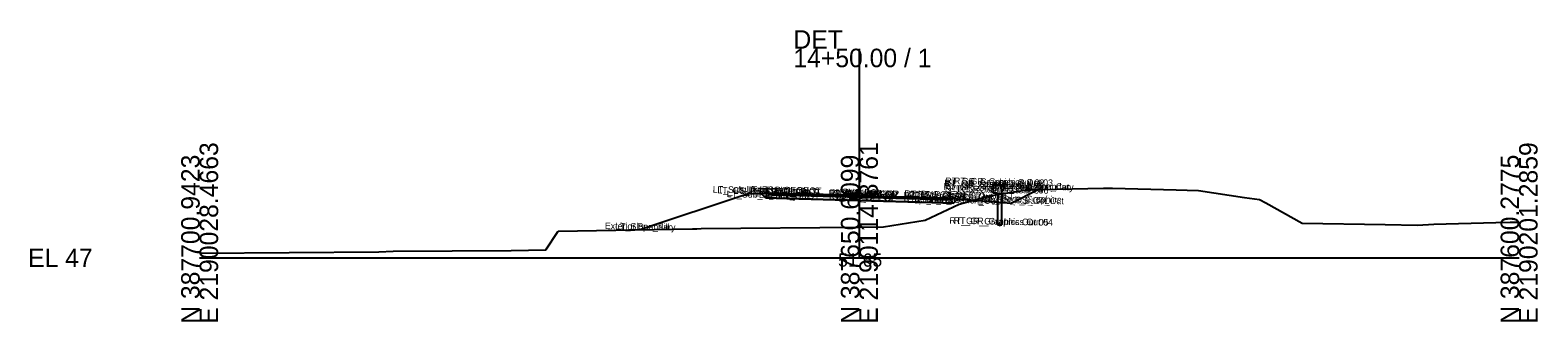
# Model space of a CAD drawing. Extents: x -26 to 1203, y -10 to 9543.
# Drawn here: x -25.7 to 202.8, y 4490.3 to 4534.5 of the extents above; entities that cross this region are included whole.
import ezdxf

# ---------------------------------------------------------------- set-up
doc = ezdxf.new("R2010")
doc.units = 0
for name, color, linetype in [('Default', 7, 'Continuous'), ('Exist Cross Section Cell', 7, 'Continuous'), ('Exist XS Center Line Elevation Label', 7, 'Continuous'), ('Exist XS Ground Line', 7, 'Continuous'), ('Prop CMT Guardrail Graphics', 7, 'Continuous'), ('Prop CMT Pvmt Course 1', 7, 'Continuous'), ('Prop CMT Pvmt Course 2', 7, 'Continuous'), ('Prop CMT Pvmt Course 3', 7, 'Continuous'), ('Prop CMT Pvmt Surface', 7, 'Continuous'), ('Prop CMT Pvmt Surface Shoulder', 7, 'Continuous'), ('Prop CMT Shld Paved Course 1', 7, 'Continuous'), ('Prop CMT Shld Paved Course 2', 7, 'Continuous'), ('Prop CMT Shld Paved Course 3', 7, 'Continuous'), ('Prop CMT Slope Grass', 7, 'Continuous'), ('Prop CMT Subgrade Earthwork', 7, 'Continuous'), ('Scratch_Level_0', 7, 'Continuous')]:
    doc.layers.add(name, color=color, linetype=linetype)

msp = doc.modelspace()

# ---------------------------------------------------------------- linework, layer by layer
at = {"layer": 'Exist Cross Section Cell'}
for p, q in [((100, 4500), (100, 4531.65)), ((0, 4500), (100, 4500)), ((100, 4500), (200, 4500))]:
    msp.add_line(p, q, dxfattribs=at)
at = {"layer": 'Exist XS Ground Line'}
for p, q in [((115.15, 4508.12), (119.71, 4509.4)), ((119.71, 4509.4), (124.76, 4510.19)), ((124.76, 4510.19), (126.04, 4510.29)), ((126.04, 4510.29), (127.51, 4510.33)), ((127.51, 4510.33), (137.02, 4510.52)), ((137.02, 4510.52), (138.38, 4510.55)), ((138.38, 4510.55), (148.04, 4510.26)), ((148.04, 4510.26), (149.7, 4510.21)), ((149.7, 4510.21), (151.41, 4510.18)), ((151.41, 4510.18), (158.37, 4509.14)), ((158.37, 4509.14), (160.65, 4508.8)), ((109.97, 4505.7), (115.15, 4508.12)), ((160.65, 4508.8), (161.63, 4508.3)), ((161.63, 4508.3), (167.13, 4505.26)), ((74.71, 4504.37), (75.38, 4504.39)), ((75.38, 4504.39), (76.04, 4504.41)), ((76.04, 4504.41), (100, 4504.65)), ((100, 4504.65), (103.65, 4504.69)), ((103.65, 4504.69), (109.97, 4505.7)), ((167.13, 4505.26), (179.69, 4505.06)), ((179.69, 4505.06), (184.61, 4504.95)), ((184.61, 4504.95), (187.08, 4505.09)), ((187.08, 4505.09), (196.47, 4505.34)), ((196.47, 4505.34), (198.66, 4505.41)), ((198.66, 4505.41), (200, 4505.38)), ((52.47, 4501.19), (54.35, 4504.03)), ((54.35, 4504.03), (74.71, 4504.37)), ((0, 4500.7), (27.17, 4500.92)), ((27.17, 4500.92), (29.32, 4501)), ((29.32, 4501), (47.24, 4501.11)), ((47.24, 4501.11), (52.47, 4501.19))]:
    msp.add_line(p, q, dxfattribs=at)
at = {"layer": 'Prop CMT Guardrail Graphics'}
for points in [[(121.59, 4511), (120.26, 4511), (119.99, 4510.71)], [(119.99, 4510.71), (120.26, 4510.42)], [(120.26, 4510.42), (119.99, 4510.13)], [(119.99, 4510.13), (120.26, 4509.84), (120.92, 4509.84)], [(120.92, 4509.84), (120.92, 4505)], [(121.59, 4505), (121.59, 4511)], [(120.92, 4505), (121.59, 4505)]]:
    msp.add_lwpolyline(points, dxfattribs=at)
at = {"layer": 'Prop CMT Pvmt Course 1'}
for points in [[(100, 4509.42), (89, 4509.73)], [(89, 4509.73), (89, 4509.48)], [(89, 4509.48), (100, 4509.17)], [(100, 4509.17), (100, 4509.42)], [(100, 4509.42), (111, 4509.12)], [(100, 4509.17), (100, 4509.42)], [(111, 4508.87), (100, 4509.17)], [(111, 4509.12), (111, 4508.87)]]:
    msp.add_lwpolyline(points, dxfattribs=at)
msp.add_lwpolyline([(100, 4509.17), (100, 4509.3), (100, 4509.3), (100, 4509.17)], close=True, dxfattribs=at)
msp.add_lwpolyline([(100, 4509.17), (100, 4509.3), (100, 4509.3), (100, 4509.17)], close=True, dxfattribs=at)
at = {"layer": 'Prop CMT Pvmt Course 2'}
for points in [[(89, 4509.48), (100, 4509.17)], [(100, 4509.17), (89, 4509.48)], [(89, 4509.48), (89, 4509.48)], [(100, 4509.17), (100, 4509.17)], [(111, 4508.87), (100, 4509.17)], [(100, 4509.17), (100, 4509.17)], [(100, 4509.17), (111, 4508.87)], [(111, 4508.87), (111, 4508.87)]]:
    msp.add_lwpolyline(points, dxfattribs=at)
at = {"layer": 'Prop CMT Pvmt Course 3'}
for points in [[(100, 4509.17), (89, 4509.48)], [(89, 4509.48), (89, 4508.98)], [(89, 4508.98), (100, 4508.67)], [(100, 4508.67), (100, 4509.17)], [(100, 4509.17), (111, 4508.87)], [(100, 4508.67), (100, 4509.17)], [(111, 4508.37), (100, 4508.67)], [(111, 4508.87), (111, 4508.37)]]:
    msp.add_lwpolyline(points, dxfattribs=at)
at = {"layer": 'Prop CMT Pvmt Surface'}
for points in [[(100, 4509.42), (89, 4509.73)], [(100, 4509.42), (111, 4509.12)]]:
    msp.add_lwpolyline(points, dxfattribs=at)
at = {"layer": 'Prop CMT Pvmt Surface Shoulder'}
for points in [[(89, 4509.73), (87, 4509.78)], [(111, 4509.12), (113, 4509.06)]]:
    msp.add_lwpolyline(points, dxfattribs=at)
at = {"layer": 'Prop CMT Shld Paved Course 1'}
for points in [[(89, 4509.73), (87, 4509.78), (86.76, 4509.54)], [(86.76, 4509.54), (89, 4509.48)], [(89, 4509.48), (89, 4509.73)], [(111, 4509.12), (113, 4509.06), (113.26, 4508.81)], [(111, 4508.87), (111, 4509.12)], [(113.26, 4508.81), (111, 4508.87)]]:
    msp.add_lwpolyline(points, dxfattribs=at)
at = {"layer": 'Prop CMT Shld Paved Course 2'}
for points in [[(89, 4509.48), (86.76, 4509.54)], [(86.76, 4509.54), (86.76, 4509.54)], [(86.76, 4509.54), (89, 4509.48)], [(89, 4509.48), (89, 4509.48)], [(111, 4508.87), (113.26, 4508.81)], [(113.26, 4508.81), (111, 4508.87)], [(111, 4508.87), (111, 4508.87)], [(113.26, 4508.81), (113.26, 4508.81)]]:
    msp.add_lwpolyline(points, dxfattribs=at)
at = {"layer": 'Prop CMT Shld Paved Course 3'}
for points in [[(89, 4509.48), (86.76, 4509.54), (86.26, 4509.55), (85.77, 4509.07)], [(85.77, 4509.07), (89, 4508.98)], [(89, 4508.98), (89, 4509.48)], [(111, 4508.87), (113.26, 4508.81), (113.76, 4508.79), (114.27, 4508.28)], [(111, 4508.37), (111, 4508.87)], [(114.27, 4508.28), (111, 4508.37)]]:
    msp.add_lwpolyline(points, dxfattribs=at)
at = {"layer": 'Prop CMT Slope Grass'}
for points in [[(87, 4509.78), (83, 4509.65), (66.74, 4504.24)], [(113, 4509.06), (122.99, 4508.26), (123, 4508.26), (127.11, 4510.32)], [(113, 4509.06), (119.99, 4508.5)], [(122.99, 4508.26), (123, 4508.26), (127.11, 4510.32)], [(119.99, 4508.5), (122.99, 4508.26)]]:
    msp.add_lwpolyline(points, dxfattribs=at)
at = {"layer": 'Prop CMT Subgrade Earthwork'}
for points in [[(85.77, 4509.07), (85.12, 4509.72)], [(89, 4508.98), (85.77, 4509.07)], [(100, 4508.67), (89, 4508.98)], [(100, 4508.67), (111, 4508.37)], [(111, 4508.37), (114.27, 4508.28)], [(114.27, 4508.28), (114.9, 4508.91)]]:
    msp.add_lwpolyline(points, dxfattribs=at)

# ---------------------------------------------------------------- texts
at = {"layer": 'Default'}
msp.add_text('-', height=0.0001, dxfattribs=at).set_placement((0, 4500))
at = {"layer": 'Exist Cross Section Cell'}
for s, p in [('DET', (90, 4531.65)), ('14+50.00 / 1', (90, 4528.85)), ('EL 47', (-26, 4498.6))]:
    msp.add_text(s, height=2.8, dxfattribs=at).set_placement(p)
for s, p in [('E 2190028.4663', (2.8, 4490)), ('E 2190114.8761', (102.8, 4490)), ('E 2190201.2859', (202.8, 4490)), ('N 387700.9423', (0, 4490)), ('N 387650.6099', (100, 4490)), ('N 387600.2775', (200, 4490))]:
    msp.add_text(s, height=2.8, rotation=90, dxfattribs=at).set_placement(p)
at = {"layer": 'Exist XS Center Line Elevation Label'}
msp.add_text('51.65', height=2, dxfattribs=at).set_placement((96.77, 4498.65))
at = {"layer": 'Scratch_Level_0'}
for s, p in [('RT_GR_Graphics Out 08', (112.7, 4510.27)), ('RT_GR_Graphics Out 01', (112.87, 4510.85)), ('RT_GR_Graphics Out 09', (112.97, 4510.56)), ('RT_GR_Graphics Out 02', (113, 4511.15)), ('RT_GR_Graphics Out 03', (114.32, 4511.15)), ('Exterior Boundary', (121.77, 4510.42)), ('RT_Slope_Cut', (123.05, 4510.4)), ('LT_Sub_Trench_Out_DLT', (77.77, 4509.87)), ('LT_GS_OS_CTL', (78.46, 4509.74)), ('LT_Sub_Trench_Out', (79.88, 4509.18)), ('LT_PS3_Shelf_Out', (80.91, 4509.66)), ('LT_PS3_OEOP', (82.54, 4509.62)), ('LT_PS2_OEOP', (82.54, 4509.62)), ('LT_PS1_OEOP', (82.91, 4509.86)), ('LT_PV2_OEOT', (84.75, 4509.56)), ('LT_PV3_OEOT', (84.75, 4509.56)), ('LT_Sub_OEOT', (84.77, 4509.06)), ('LT_PV1_OEOT', (84.87, 4509.81)), ('RT_PV2_OEEOP', (95.33, 4509.26)), ('RT_PV3_OEEOP', (95.33, 4509.26)), ('RT_Sub_OEEOP', (95.36, 4508.76)), ('LT_PV2_OEEOP', (95.39, 4509.26)), ('LT_PV3_OEEOP', (95.39, 4509.26)), ('LT_Sub_OEEOP', (95.42, 4508.76)), ('RT_PV1_OEEOP', (95.45, 4509.39)), ('LT_PV1_OEEOP', (95.51, 4509.39)), ('RT_PV2_IEEOP', (95.71, 4509.26)), ('LT_PV2_IEEOP', (95.77, 4509.26)), ('RT_PV1_IEEOP', (95.83, 4509.38)), ('LT_PV1_IEEOP', (95.89, 4509.38)), ('PV2_PGL', (97.35, 4509.23)), ('PV1_PGL', (97.47, 4509.47)), ('RT_PV3_OEOT', (106.69, 4508.95)), ('RT_PV2_OEOT', (106.69, 4508.95)), ('RT_Sub_OEOT', (106.71, 4508.45)), ('RT_PV1_OEOT', (106.81, 4509.2)), ('RT_Sub_Trench_Out_DLT', (107.5, 4509.06)), ('RT_Sub_Trench_Out', (108.32, 4508.39)), ('RT_PS3_Shelf_Out', (108.36, 4508.9)), ('RT_PS1_OEOP', (108.85, 4509.14)), ('RT_PS3_OEOP', (108.99, 4508.89)), ('RT_PS2_OEOP', (108.99, 4508.89)), ('RT_GS_OS_GR_Face_Graphics', (110.92, 4508.68)), ('RT_GR_Graphics Out 07', (112.96, 4509.98)), ('RT_GR_Graphics Out 06', (113.64, 4509.98)), ('RT_SS_Ditch_Base_Out', (116.19, 4508.39)), ('RT_GS_OS_CTL', (118.39, 4508.35)), ('Exterior Boundary', (61.41, 4504.34)), ('LT_Slope_Fill', (62.98, 4504.31)), ('RT_GR_Graphics Out 05', (113.64, 4505.15)), ('RT_GR_Graphics Out 04', (114.3, 4505.15))]:
    msp.add_text(s, height=1, rotation=358.8836, dxfattribs=at).set_placement(p)

doc.saveas('drawing.dxf')
